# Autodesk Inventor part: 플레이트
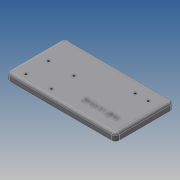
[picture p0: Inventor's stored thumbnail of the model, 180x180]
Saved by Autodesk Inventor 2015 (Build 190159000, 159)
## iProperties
Created: 2018-01
Part Number: 플레이트
Material: 알루미늄 6061
Document SubType Name: Modeling
Designer: mduedu
Density: 2.71 g/cm^3
Appearance: 기본값
Author: mduedu
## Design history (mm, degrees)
sketch "스케치1"
  geometry: L1 (75, 40)-(-75, 40); L2 (-75, 40)-(-75, -40); L3 (-75, -40)-(75, -40); L4 (75, -40)-(75, 40); L5 (75, 40)-(-75, -40); L6 (-75, 40)-(75, -40); 1 further point
  constraints: 12 end point, 2 midpoint, 2 parallel, 1 horizontal, 1 perpendicular
  dimensions: "d0" = 150 distance of L3.end L2.end; "d1" = 80 distance of L2.end L1.end
extrude "돌출1" new body sketch "스케치1" distance "d2" = 10; taper "d3" = 0 deg
fillet "모깎기1" dims "d4" = 5
fillet "모깎기2" dims "d5" = 3
sketch "스케치2"
  geometry: L1 (-70, 40)-(70, 40) reference; L2 (-75, -35)-(-75, 35) reference; 5 further points
  constraints: 2 horizontal alignment, 2 vertical alignment
  dimensions: "d6" = 10 distance from line of point (-58, 30) L1; "d7" = 35 distance of point (-23, 30) point (-58, 30); "d8" = 31 distance of point (-58, -1) point (-58, 30); "d9" = 17 distance from line of point (-58, 30) L2
sketch "스케치3"
  geometry: 4 further points
  constraints: 4 other
hole "구멍1" sketch "스케치3" at (-23, 30), (-58, -1), (-23, -1), (-58, 30) diameter "d10" = 3.4; stored, may be unused: countersink angle "d14" = 90 deg, drill point angle "d16" = 0 deg; dims "d11" = 6, "d12" = 6.5, "d13" = 3.4, "d15" = 8
sketch "스케치4"
  geometry: L1 (75, 35)-(75, -35) reference; L2 (70, -40)-(-70, -40) reference; 3 further points
  constraints: 1 horizontal alignment
  dimensions: "d17" = 17 distance from line of point (58, -22) L1; "d18" = 18 distance of point (40, -22) point (58, -22); "d19" = 18 distance from line of point (58, -22) L2
sketch "스케치5"
  geometry: 2 further points
  constraints: 2 other
hole "구멍2" sketch "스케치5" at (40, -22), (58, -22) diameter "d20" = 3.4; stored, may be unused: countersink angle "d24" = 90 deg, drill point angle "d26" = 0 deg; dims "d21" = 6, "d22" = 6.5, "d23" = 3.4, "d25" = 8
sketch "스케치6"
  geometry: L1 (75, -35)-(75, 35) reference; L2 (-70, -40)-(70, -40) reference; 2 further points
  constraints: 1 other
  dimensions: "d27" = 40 distance from line of point (35, -20) L1; "d28" = 20 distance from line of point (35, -20) L2
feature "엠보싱1" sketch "스케치6" dims "d0" = 150, "d29" = 0.5, "d30" = 0
node "솔리드1"
